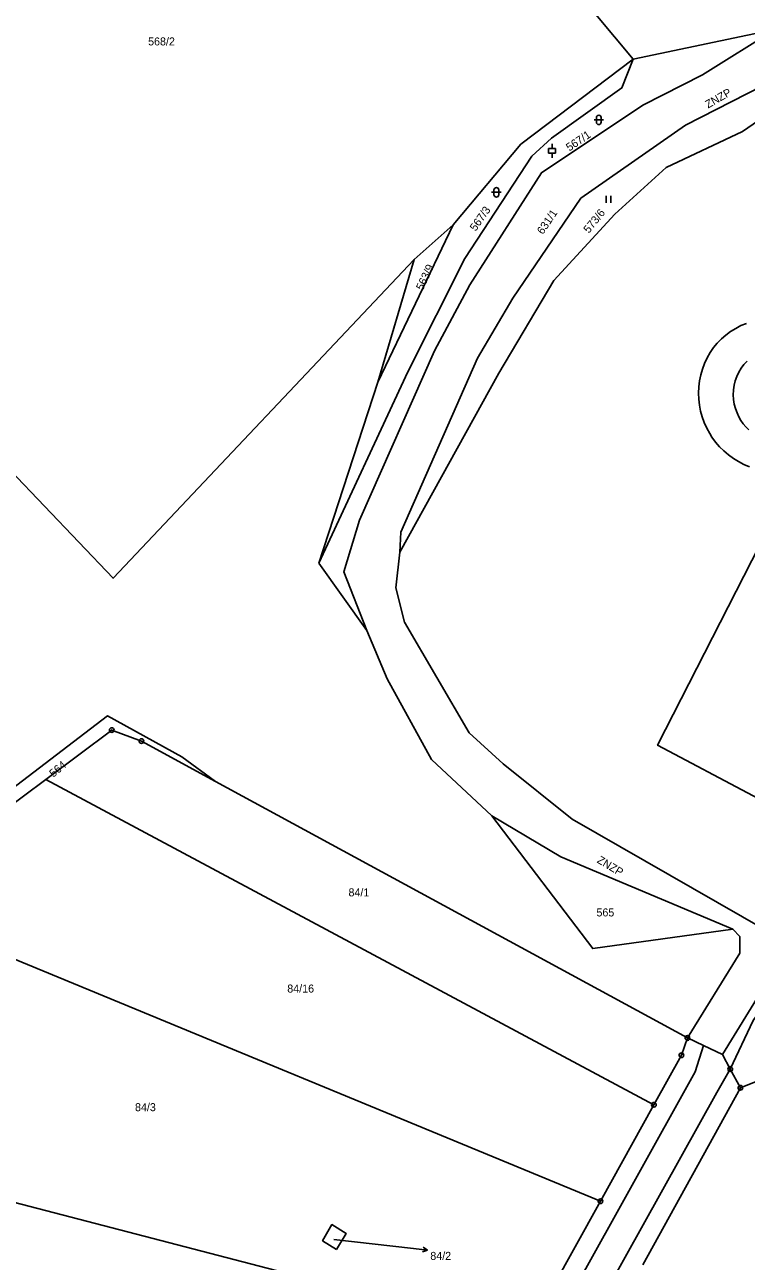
# Model space of a CAD drawing. Extents: x -758582 to -751794, y -998770 to -994350.
# Drawn here: x -756148.4 to -755995.1, y -996103.7 to -995841.1 of the extents above; entities that cross this region are included whole.
import ezdxf

# ---------------------------------------------------------------- set-up
doc = ezdxf.new("R2010")
doc.units = 0
for name, color, linetype in [('Hranice parcel', 7, 'Continuous'), ('Parcelní čísla', 7, 'Continuous'), ('Pop  PČ popisy', 7, 'Continuous'), ('Vnitřní kresba', 7, 'Continuous'), ('Značky bodu BP', 7, 'Continuous'), ('Značky kultur', 7, 'Continuous')]:
    doc.layers.add(name, color=color, linetype=linetype)

msp = doc.modelspace()

# ---------------------------------------------------------------- linework, layer by layer
at = {"layer": 'Hranice parcel'}
for p, q in [((-755988.7, -995841.97), (-756019.11, -995848.38)), ((-756057.34, -995883.55), (-756073.34, -995916.98)), ((-756057.34, -995883.55), (-756065.63, -995890.95)), ((-756065.63, -995890.95), (-756073.34, -995916.98)), ((-756073.34, -995916.98), (-756085.91, -995955.47)), ((-756085.91, -995955.47), (-756075.68, -995969.76)), ((-756107.85, -996001.82), (-756123.61, -995993.25)), ((-756107.85, -996001.82), (-756123.61, -995993.25)), ((-756143.92, -996001.41), (-756153.37, -996008.5)), ((-756143.92, -996001.41), (-756153.37, -996008.5)), ((-756143.92, -996001.41), (-756014.7, -996070.51)), ((-756007.59, -996056.31), (-756107.85, -996001.82)), ((-756007.59, -996056.31), (-756107.85, -996001.82)), ((-756026.07, -996090.99), (-756174.39, -996029.74)), ((-755985.78, -996036.35), (-756000.15, -996059.81)), ((-755985.78, -996036.35), (-756000.15, -996059.81)), ((-756000.15, -996059.81), (-755998.48, -996062.9)), ((-755998.48, -996062.9), (-755996.34, -996066.87)), ((-755996.34, -996066.87), (-756017.1, -996104.51)), ((-756014.7, -996070.51), (-756026.07, -996090.99)), ((-756215.02, -996074.51), (-756041.85, -996119.46)), ((-756026.07, -996090.99), (-756041.85, -996119.46))]:
    msp.add_line(p, q, dxfattribs=at)
for points in [[(-756019.11, -995848.38), (-756042.22, -995820.69), (-756054.42, -995807.4), (-756075.71, -995786.64), (-756095.61, -995763.32), (-756108.62, -995745.03)], [(-755957.41, -995832.15), (-755978.63, -995847.4), (-756008.02, -995862.42), (-756030.26, -995877.93), (-756044.68, -995899.13), (-756052.22, -995911.9), (-756068.45, -995948.84), (-756068.67, -995953.08)], [(-755954.75, -995832.96), (-755955.85, -995836.29), (-755995.87, -995863.75), (-756012.13, -995871.42), (-756023.02, -995881.32), (-756035.99, -995895.37), (-756047.63, -995915.1), (-756068.67, -995953.08)], [(-756075.68, -995969.76), (-756080.62, -995957.32), (-756077.28, -995946.3), (-756061.36, -995910.37), (-756053.83, -995896.3), (-756038.56, -995872.5), (-756017.08, -995858.16), (-756004.36, -995851.68), (-755988.7, -995841.97)], [(-756019.11, -995848.38), (-756021.51, -995854.49), (-756036.48, -995865.15), (-756040.62, -995869.02), (-756054.87, -995890.7), (-756067, -995914.83), (-756085.91, -995955.47)], [(-756019.11, -995848.38), (-756042.98, -995866.43), (-756057.34, -995883.55)], [(-756065.63, -995890.95), (-756129.62, -995958.65), (-756231.79, -995851.55)], [(-755994.4, -995934.96), (-755995.59, -995934.46), (-755996.74, -995933.88), (-755997.83, -995933.2), (-755998.88, -995932.45), (-755999.86, -995931.61), (-756000.77, -995930.7), (-756001.61, -995929.72), (-756002.37, -995928.68), (-756002.86, -995927.9), (-756003.48, -995926.77), (-756004.01, -995925.6), (-756004.44, -995924.38), (-756004.78, -995923.14), (-756005.02, -995921.87), (-756005.16, -995920.59), (-756005.21, -995919.3), (-756005.15, -995918.02), (-756004.99, -995916.74), (-756004.74, -995915.47), (-756004.38, -995914.23), (-756003.94, -995913.03), (-756003.39, -995911.86), (-756002.77, -995910.73), (-756002.05, -995909.66), (-756001.24, -995908.7), (-756000.36, -995907.8), (-755999.42, -995906.98), (-755998.41, -995906.23), (-755997.34, -995905.57), (-755996.22, -995904.99), (-755995.06, -995904.51)], [(-755994.53, -995927.1), (-755995.18, -995926.5), (-755995.77, -995925.84), (-755996.27, -995925.12), (-755996.69, -995924.34), (-755997.02, -995923.52), (-755997.38, -995922.6), (-755997.64, -995921.64), (-755997.8, -995920.66), (-755997.87, -995919.67), (-755997.83, -995918.68), (-755997.83, -995918.64), (-755997.69, -995917.66), (-755997.46, -995916.7), (-755997.12, -995915.77), (-755996.7, -995914.87), (-755996.19, -995914.02), (-755995.59, -995913.23), (-755994.93, -995912.55)], [(-755973.27, -996015.65), (-756013.93, -995994.11), (-755983.91, -995935.32)], [(-756068.67, -995953.08), (-756069.56, -995960.68), (-756067.71, -995967.98), (-756053.95, -995991.46), (-756046.76, -995998.06), (-756032.07, -996009.82), (-755985.78, -996036.35)], [(-756075.68, -995969.76), (-756071.39, -995980.05), (-756061.95, -995997.14), (-756049.14, -996009.12)], [(-756107.85, -996001.82), (-756115.03, -995996.57), (-756130.82, -995987.89), (-756153.74, -996005.4), (-756159.4, -996000.79), (-756169.66, -995990.8)], [(-756123.61, -995993.25), (-756129.91, -995990.9), (-756143.92, -996001.41)], [(-756123.61, -995993.25), (-756129.91, -995990.9), (-756143.92, -996001.41)], [(-756049.14, -996009.12), (-756034.46, -996017.8), (-755997.92, -996033.16)], [(-756049.14, -996009.12), (-756027.69, -996037.31), (-755997.92, -996033.16)], [(-755997.92, -996033.16), (-755996.48, -996034.76), (-755996.48, -996038.31), (-756007.59, -996056.31)], [(-755963.59, -996046.51), (-755978.88, -996045.81), (-755990.46, -996047.99), (-755993.62, -996052.63), (-755998.48, -996062.9)], [(-755950.94, -996054.8), (-755977.82, -996059.45), (-755996.34, -996066.87)], [(-756007.59, -996056.31), (-756008.87, -996059.99), (-756014.7, -996070.51)], [(-756000.15, -996059.81), (-756004.21, -996057.9), (-756007.59, -996056.31)], [(-756000.15, -996059.81), (-756004.21, -996057.9), (-756007.59, -996056.31)], [(-756082.14, -996101.25), (-756080.1, -996097.81), (-756083.11, -996095.96), (-756085.1, -996099.37), (-756082.14, -996101.25)]]:
    msp.add_lwpolyline(points, dxfattribs=at)
at = {"layer": 'Pop  PČ popisy'}
for p, q in [((-756082.7, -996099.15), (-756065.8, -996101.05)), ((-756065.8, -996101.05), (-756062.82, -996101.36)), ((-756062.82, -996101.36), (-756063.86, -996101.76)), ((-756062.82, -996101.36), (-756063.76, -996100.76))]:
    msp.add_line(p, q, dxfattribs=at)
at = {"layer": 'Vnitřní kresba'}
for p, q in [((-756005.96, -996063.5), (-756004.21, -996057.9)), ((-756046.58, -996136.62), (-756005.96, -996063.5)), ((-756001.34, -996067.9), (-755998.48, -996062.9)), ((-756001.34, -996067.9), (-756036.37, -996130.79))]:
    msp.add_line(p, q, dxfattribs=at)
at = {"layer": 'Značky bodu BP'}
for centre, radius in [((-756129.91, -995990.9), 0.5), ((-756129.91, -995990.9), 0.0303), ((-756123.61, -995993.25), 0.5), ((-756123.61, -995993.25), 0.0303), ((-756007.59, -996056.31), 0.5), ((-756007.59, -996056.31), 0.0303), ((-756008.87, -996059.99), 0.5), ((-756008.87, -996059.99), 0.0303), ((-755998.48, -996062.9), 0.5), ((-755998.48, -996062.9), 0.0303), ((-755996.34, -996066.87), 0.5), ((-755996.34, -996066.87), 0.0303), ((-756014.7, -996070.51), 0.5), ((-756014.7, -996070.51), 0.0303), ((-756026.07, -996090.99), 0.5), ((-756026.07, -996090.99), 0.0303)]:
    msp.add_circle(centre, radius, dxfattribs=at)
at = {"layer": 'Značky kultur'}
for p, q in [((-756027.42, -995861.28), (-756025.42, -995861.28)), ((-756026.92, -995860.78), (-756026.92, -995861.78)), ((-756025.92, -995861.78), (-756025.92, -995860.78)), ((-756037.1, -995867.36), (-756035.6, -995867.36)), ((-756037.1, -995868.36), (-756037.1, -995867.36)), ((-756037.1, -995868.36), (-756035.6, -995868.36)), ((-756036.35, -995867.36), (-756036.35, -995866.36)), ((-756036.35, -995869.36), (-756036.35, -995868.36)), ((-756035.6, -995868.36), (-756035.6, -995867.36)), ((-756048.69, -995876.17), (-756048.69, -995877.17)), ((-756047.69, -995877.17), (-756047.69, -995876.17)), ((-756049.19, -995876.67), (-756047.19, -995876.67)), ((-756024.83, -995878.89), (-756024.83, -995877.39)), ((-756023.83, -995878.89), (-756023.83, -995877.39))]:
    msp.add_line(p, q, dxfattribs=at)
for centre, start, end in [((-756026.42, -995860.78), 0, 180), ((-756026.42, -995861.78), 180, 359.9879), ((-756048.19, -995876.17), 0, 180), ((-756048.19, -995877.17), 180, 359.9879)]:
    msp.add_arc(centre, 0.5, start, end, dxfattribs=at)

# ---------------------------------------------------------------- texts
at = {"layer": 'Parcelní čísla'}
for s, p in [('568/2', (-756122.18, -995845.47)), ('84/1', (-756079.6, -996026.23)), ('565', (-756026.92, -996030.49)), ('84/16', (-756092.61, -996046.66)), ('84/3', (-756124.96, -996071.86)), ('84/2', (-756062.22, -996103.45))]:
    msp.add_text(s, height=1.7, dxfattribs=at).set_placement(p)
for s, rotation, p in [('567/1', 34, (-756032.67, -995868.03)), ('567/3', 55, (-756052.58, -995885.06)), ('631/1', 56, (-756038.29, -995885.75)), ('573/6', 51, (-756028.54, -995885.49)), ('563/9', 65, (-756063.81, -995897.63)), ('564', 40, (-756142.31, -996001.04))]:
    msp.add_text(s, height=1.7, rotation=rotation, dxfattribs=at).set_placement(p)
at = {"layer": 'Pop  PČ popisy'}
for rotation, p in [(30, (-756003.2, -995858.89)), (329, (-756026.96, -996018.96))]:
    msp.add_text('ZNZP', height=1.7, rotation=rotation, dxfattribs=at).set_placement(p)

doc.saveas('drawing.dxf')
